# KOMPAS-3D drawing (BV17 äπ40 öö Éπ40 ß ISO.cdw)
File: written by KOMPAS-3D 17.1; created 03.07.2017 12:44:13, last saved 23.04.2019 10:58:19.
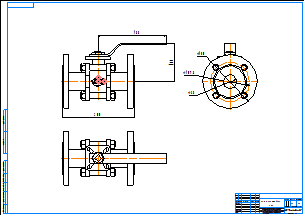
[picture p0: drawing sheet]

Sheet 1: A1, landscape

Title block, sheet 1: name: BV17 Ду40 ФФ Ру40 / с ISO; material: Внимание! Данный продукт является объектом авторского права ООО «Торговый Дом АДЛ». / Запрещается изменение, копирование, распространение / (в том числе путем копирования на другие сайты и ресурсы в Интернете) / или любое иное использование информации и объектов без предварительного / согласия правообладателя (ООО «Торговый Дом АДЛ»).; mass: 1,7; sheets: 1; organisation: ООО "Торговый дом АДЛ"; sheet format: A1; stored path: C:\Users\kka\KOMPAS_Work\!Trash\СС02 СС03 ФФ Смотровые стекла\СС01.cdw

Views: Спереди 1, Проекционный вид 2, Проекционный вид 3
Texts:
  Klimkovich
  ADL
Dimensions and other numbers on the sheet: 200; 188; 107; 109,8; 150; 38; 1:1; 1; 1,7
